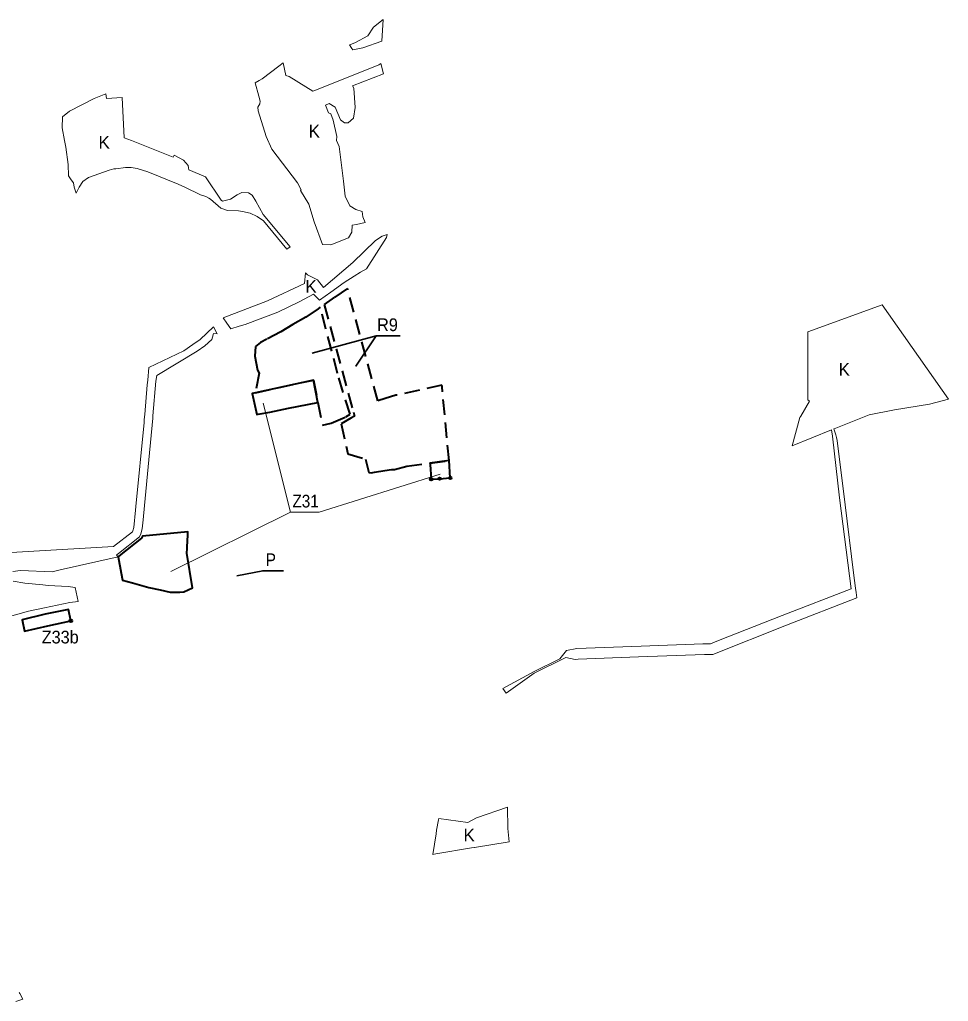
# Model space of a CAD drawing. Extents: x -650276 to -642489, y -1074311 to -1066658.
# Drawn here: x -644235 to -642489, y -1070870 to -1069023 of the extents above; entities that cross this region are included whole.
import ezdxf

# ---------------------------------------------------------------- set-up
doc = ezdxf.new("R2010")
doc.units = 0
doc.header["$LTSCALE"] = 9.6
doc.header["$PDMODE"] = 32
doc.header["$PDSIZE"] = 4.8
doc.linetypes.add('MEDIUM_DASHED', pattern=[4.5, 3, -1.5])
for name, color, linetype, lineweight in [('3', 7, 'Continuous', 40), ('45', 7, 'Continuous', 40), ('46', 7, 'Continuous', 13), ('47', 7, 'Continuous', 13), ('48', 7, 'Continuous', 35), ('59', 7, 'Continuous', 13), ('60', 7, 'Continuous', 35), ('61', 7, 'MEDIUM_DASHED', 40), ('62', 7, 'Continuous', 35)]:
    doc.layers.add(name, color=color, linetype=linetype, lineweight=lineweight)

msp = doc.modelspace()

# ---------------------------------------------------------------- linework, layer by layer
at = {"layer": '3'}
for p, q in [((-643461.327, -1069887.84), (-643445.37, -1069886.7)), ((-643445.37, -1069886.7), (-643425.253, -1069885.25))]:
    msp.add_line(p, q, dxfattribs=at)
for points in [[(-643425.253, -1069885.25), (-643427.6, -1069852.59), (-643463.51, -1069857.44)], [(-643463.51, -1069857.44), (-643463.31, -1069860.18), (-643461.327, -1069887.84)]]:
    msp.add_lwpolyline(points, dxfattribs=at)
for p in [(-643461.327, -1069887.84), (-643445.37, -1069886.7), (-643425.253, -1069885.25)]:
    msp.add_point(p, dxfattribs=at)
at = {"layer": '45'}
for p, q in [((-644138.78, -1070154.07), (-644143.31, -1070132.95)), ((-644182.31, -1070163.66), (-644138.78, -1070154.07))]:
    msp.add_line(p, q, dxfattribs=at)
for points in [[(-643791.88, -1069725.25), (-643797.75, -1069726.51), (-643789.3, -1069766.05), (-643786.35, -1069765.46), (-643764.94, -1069761.27), (-643729.34, -1069754.3), (-643674.3, -1069743.53), (-643682.61, -1069701.16)], [(-643791.88, -1069725.25), (-643797.75, -1069726.51), (-643789.3, -1069766.05), (-643786.35, -1069765.46), (-643764.94, -1069761.27), (-643729.34, -1069754.3), (-643674.3, -1069743.53), (-643682.61, -1069701.16)], [(-643920.84, -1070026.46), (-643920.29, -1070017.73), (-643920.16, -1070015.69), (-643918.69, -1069992.23), (-643918.88, -1069986.82), (-644004.06, -1069994.59), (-644005.92, -1069998.62), (-644044.7, -1070029.04), (-644050.12, -1070033.64), (-644044.18, -1070064.43), (-644041.71, -1070077.29), (-644022.77, -1070082.66), (-643991.99, -1070091.37), (-643971.03, -1070095.79), (-643951.99, -1070100.35), (-643933.96, -1070100.18), (-643926.33, -1070099.5), (-643909.87, -1070091.95)], [(-643920.84, -1070026.46), (-643920.29, -1070017.73), (-643920.16, -1070015.69), (-643918.69, -1069992.23), (-643918.88, -1069986.82), (-644004.06, -1069994.59), (-644005.92, -1069998.62), (-644044.7, -1070029.04), (-644050.12, -1070033.64), (-644044.18, -1070064.43), (-644041.71, -1070077.29), (-644022.77, -1070082.66), (-643991.99, -1070091.37), (-643971.03, -1070095.79), (-643951.99, -1070100.35), (-643933.96, -1070100.18), (-643926.33, -1070099.5), (-643909.87, -1070091.95)]]:
    msp.add_lwpolyline(points, close=True, dxfattribs=at)
for points in [[(-644143.31, -1070132.95), (-644143.31, -1070132.95), (-644143.31, -1070132.95), (-644187.11, -1070141.58), (-644230.4, -1070152.08), (-644226.23, -1070173.28), (-644182.31, -1070163.66)], [(-644143.31, -1070132.95), (-644143.31, -1070132.95), (-644143.31, -1070132.95), (-644187.11, -1070141.58), (-644230.4, -1070152.08), (-644226.23, -1070173.28), (-644182.31, -1070163.66)], [(-644182.31, -1070163.66), (-644138.78, -1070154.07), (-644143.31, -1070132.95)]]:
    msp.add_lwpolyline(points, dxfattribs=at)
msp.add_point((-644138.78, -1070154.07), dxfattribs=at)
at = {"layer": '46'}
msp.add_lwpolyline([(-643672.005, -1069949.473), (-643725.65, -1069949.473), (-643725.65, -1069949.473), (-643777.096, -1069744.435), (-643725.65, -1069949.473), (-643950.635, -1070061)], dxfattribs=at)
at = {"layer": '47'}
msp.add_line((-643785.6, -1069166.98), (-643782.92, -1069176.24), dxfattribs=at)
msp.add_lwpolyline([(-643589.94, -1069076.36), (-643554.17, -1069063.59), (-643551.72, -1069023.19), (-643569.44, -1069037.24), (-643580.21, -1069053.96), (-643603.72, -1069066.5), (-643614.36, -1069070.29), (-643614.82, -1069070.45), (-643610.31, -1069077.52), (-643608.65, -1069080.11)], close=True, dxfattribs=at)
for points in [[(-643697.29, -1069149.7), (-643728.49, -1069129.95), (-643734.75, -1069128.3), (-643739.66, -1069104.58), (-643747.75, -1069110.71), (-643779.31, -1069134.63), (-643784.55, -1069137.77), (-643792.04, -1069142.27), (-643785.6, -1069166.98)], [(-643555.98, -1069105.57), (-643559.5, -1069107.98), (-643610.81, -1069129.04), (-643681.63, -1069157.04), (-643683.68, -1069157.86), (-643697.29, -1069149.7)], [(-643607.02, -1069152.34), (-643609.08, -1069147.64), (-643550.79, -1069125.24), (-643555.98, -1069105.57)], [(-643707.23, -1069344.52), (-643691.6, -1069370.3), (-643681.09, -1069403.24), (-643665.87, -1069446.1), (-643650.28, -1069446.91), (-643616.78, -1069433.81), (-643610.18, -1069422.91), (-643609.6, -1069409.99), (-643601.9, -1069408.43), (-643585.19, -1069404.76), (-643589.52, -1069393.88), (-643590.89, -1069383.9), (-643602.92, -1069380.53), (-643614.35, -1069373.28), (-643623.28, -1069355.47), (-643625.9, -1069326.77), (-643634.56, -1069262.02), (-643639.23, -1069250.38), (-643638.72, -1069242.94), (-643645.61, -1069212.25), (-643649.84, -1069200.4), (-643654.57, -1069198.77), (-643660.22, -1069184.11), (-643653.05, -1069180.98), (-643641.84, -1069187.68), (-643631.66, -1069211.67), (-643624.38, -1069217.27), (-643617.64, -1069217), (-643607.37, -1069208.43), (-643604.38, -1069188.48), (-643607.02, -1069152.34)], [(-644094.79, -1069171.27), (-644141.24, -1069195.17), (-644154.36, -1069206.06), (-644155.37, -1069226.72), (-644151.11, -1069250.7), (-644148.22, -1069263.22), (-644144.05, -1069295.67)], [(-644024.93, -1069250.23), (-644038.83, -1069245.65), (-644042.37, -1069169.77), (-644071.97, -1069171.72), (-644073.35, -1069162.84), (-644094.79, -1069171.27)], [(-643782.92, -1069176.24), (-643783.2, -1069181.85), (-643786.97, -1069188.11), (-643786.89, -1069195.02), (-643771.86, -1069242.77), (-643761.21, -1069267.12), (-643712.78, -1069330.24)], [(-643732.705, -1069454.79), (-643726.74, -1069450.72), (-643777.27, -1069389.71), (-643791.02, -1069364.54), (-643798.1, -1069353.51), (-643804.83, -1069348.99), (-643817.06, -1069348.14), (-643826.21, -1069352.92), (-643838.69, -1069360.79), (-643853.56, -1069364.44), (-643856.43, -1069362.68), (-643885.63, -1069318.72), (-643916.78, -1069305.89), (-643917.36, -1069302.04), (-643918.08, -1069297.33), (-643926.74, -1069287.37), (-643944.89, -1069278.32), (-643946.16, -1069281.84), (-644015.12, -1069254.24), (-644024.93, -1069250.23)], [(-644144.05, -1069295.67), (-644143.54, -1069317.05), (-644138.55, -1069324.23), (-644134.15, -1069330.45), (-644132.52, -1069338.02), (-644129.09, -1069349.83), (-644123.21, -1069338.41), (-644116.33, -1069327.36), (-644105.5, -1069320.03), (-644067.08, -1069306.15)], [(-644067.08, -1069306.15), (-644058.05, -1069304.02), (-644054.35, -1069303.55)], [(-644054.35, -1069303.55), (-644035.89, -1069301.02), (-644025.24, -1069301.38), (-644014.19, -1069303.36), (-643993.91, -1069309.57), (-643936.87, -1069332.93), (-643924.42, -1069338.29), (-643894.84, -1069352.76), (-643885.22, -1069355.58), (-643879.48, -1069359.13), (-643876.34, -1069360.61), (-643856.58, -1069377.59), (-643844.28, -1069382.26), (-643823.72, -1069382.61), (-643815.93, -1069384.23), (-643801.36, -1069387.23), (-643788.63, -1069393.7), (-643776.78, -1069401.87), (-643732.705, -1069454.79)], [(-643712.78, -1069330.24), (-643705.74, -1069343.54), (-643707.23, -1069344.52)], [(-643671.53, -1069551.1), (-643649.94, -1069535.93), (-643624.65, -1069517.85), (-643605.97, -1069505.47), (-643594.49, -1069498.17), (-643582.77, -1069491.76), (-643545.07, -1069432.89), (-643544.06, -1069427.6), (-643553.7, -1069430.44), (-643565.92, -1069438.4), (-643608.89, -1069479.72), (-643663.46, -1069526.87), (-643675.32, -1069512.62), (-643693.95, -1069503.38)], [(-643693.95, -1069503.38), (-643697.85, -1069499.21), (-643699.23, -1069519.48), (-643769.08, -1069551.96), (-643852.51, -1069584.08), (-643845.304, -1069594.087)], [(-643845.304, -1069594.087), (-643837.72, -1069604.62), (-643822.06, -1069600.07), (-643811.16, -1069596.45), (-643749.64, -1069573.35), (-643709.33, -1069554.14), (-643682.27, -1069539.41), (-643671.53, -1069551.1)], [(-642704.1, -1069793.095), (-642703.57, -1069792.88), (-642693.99, -1069788.85), (-642637.44, -1069766.81), (-642589.86, -1069757.1), (-642524.14, -1069746.8), (-642488.71, -1069736.85), (-642613.34, -1069559.68), (-642753.18, -1069610.65), (-642753.25, -1069738.59), (-642750.08, -1069740.57), (-642766.27, -1069769), (-642767.89, -1069771.42), (-642782.69, -1069824.93)], [(-644248.05, -1070061.33), (-644233.51, -1070059.54), (-644174.12, -1070062.16), (-644159.02, -1070057.84), (-644050.12, -1070033.64), (-644053.18, -1070030.57), (-644051.913, -1070029.549), (-644049.311, -1070027.453), (-644009.95, -1069995.74), (-644006.96, -1069990.34), (-644005.06, -1069981.28), (-644003.06, -1069964.06), (-644000.52, -1069937.19), (-643992.27, -1069851.31), (-643984.845, -1069772.863), (-643984.44, -1069768.58), (-643978.85, -1069703.4), (-643977.454, -1069692.683), (-643901.55, -1069646.92), (-643886.62, -1069636.87), (-643873.82, -1069625.05), (-643872.55, -1069620.75), (-643870.44, -1069613.56), (-643863.92, -1069613.9), (-643870.697, -1069601.241), (-643895.951, -1069625.069), (-643909.616, -1069634.267), (-643926.229, -1069646.367), (-643992.34, -1069677.76), (-643994.36, -1069701.05), (-643995.17, -1069710.42), (-643999.94, -1069765.62), (-644000.79, -1069775.42), (-644001.04, -1069778.063), (-644001.29, -1069780.7), (-644016.47, -1069938.99), (-644017.15, -1069945.93), (-644020.26, -1069978.38), (-644022.43, -1069984.87), (-644022.99, -1069986.58), (-644058.55, -1070014.4), (-644219.33, -1070023.53), (-644370.87, -1070032.13)], [(-642706.3, -1069806.69), (-642693.2, -1069922.89), (-642671.23, -1070094.16), (-642801.19, -1070143.75), (-642921.03, -1070191.32), (-642936.02, -1070197.23), (-642942.12, -1070197.4), (-642950.42, -1070197.58), (-643066.26, -1070201.69), (-643187.06, -1070205.98)], [(-642782.69, -1069824.93), (-642708.257, -1069794.779), (-642706.3, -1069806.69)], [(-642662.32, -1070100.64), (-642663.28, -1070092.67), (-642667.19, -1070063.71), (-642682.78, -1069935.98), (-642697.64, -1069815.14), (-642698.77, -1069809.17), (-642700.34, -1069804.12), (-642704.1, -1069793.095)], [(-644381.21, -1070181.71), (-644218.65, -1070135.75), (-644188.44, -1070129.43), (-644140.72, -1070119.57), (-644125, -1070117.83), (-644130.91, -1070091.1), (-644144.13, -1070089.47), (-644181.81, -1070087.51), (-644191.26, -1070086.47), (-644225.13, -1070082.95), (-644247.3, -1070079.69)], [(-642936.88, -1070217.27), (-642931.88, -1070217.1), (-642792.87, -1070162.36), (-642661.13, -1070110.48), (-642662.32, -1070100.64)], [(-643187.06, -1070205.98), (-643207.1, -1070209.72), (-643219.4, -1070225.8), (-643267.55, -1070249.49), (-643326.26, -1070281.43), (-643320, -1070290.2), (-643267.75, -1070252.77), (-643208.09, -1070223.14), (-643190.42, -1070226.99)], [(-643190.42, -1070226.99), (-643184.86, -1070225.91), (-643071.16, -1070221.95), (-642947.42, -1070217.64), (-642936.88, -1070217.27)], [(-643452.22, -1070592.35), (-643385.72, -1070580.86), (-643380.35, -1070580.14), (-643380.08, -1070580.09), (-643314.51, -1070569.69), (-643315.27, -1070563.2), (-643317.08, -1070544.75), (-643317.9, -1070504.73)], [(-643317.9, -1070504.73), (-643376.07, -1070524.59), (-643392.41, -1070533.68), (-643446.89, -1070526.01)], [(-643446.89, -1070526.01), (-643447.79, -1070528.63), (-643450.98, -1070547.74), (-643452.14, -1070554.77)], [(-643452.14, -1070554.77), (-643458.42, -1070593.43), (-643452.22, -1070592.35)], [(-644242.29, -1070869.82), (-644229.12, -1070865.52), (-644234.66, -1070855.08), (-644236.3, -1070852.87)]]:
    msp.add_lwpolyline(points, dxfattribs=at)
at = {"layer": '59'}
msp.add_lwpolyline([(-643444.15, -1069878.232), (-643672.005, -1069949.473), (-643725.65, -1069949.473)], dxfattribs=at)
at = {"layer": '60'}
msp.add_lwpolyline([(-643738.691, -1070059.84), (-643778.124, -1070059.84), (-643826.476, -1070069.235)], dxfattribs=at)
msp.add_lwpolyline([(-643738.691, -1070059.84), (-643778.124, -1070059.84), (-643826.476, -1070069.235)], dxfattribs=at)
at = {"layer": '61'}
for points in [[(-643561.41, -1069740.406), (-643618.737, -1069528.647), (-643643.16, -1069545.42), (-643662.335, -1069558.944), (-643607.44, -1069761.72), (-643605.24, -1069768.92), (-643612.22, -1069772.9), (-643630.77, -1069783.44), (-643618, -1069840.01), (-643584.63, -1069849.66), (-643578.28, -1069874.97), (-643574.05, -1069875.85), (-643567.91, -1069874.7), (-643548.67, -1069871.08), (-643535.83, -1069869.23), (-643530.01, -1069869.17), (-643507.1, -1069863.33), (-643463.51, -1069857.44), (-643427.6, -1069852.59), (-643440.77, -1069713.85), (-643441.08, -1069710.59), (-643527.49, -1069729.78), (-643547.9, -1069735.62)], [(-643743.81, -1069610.19), (-643770.29, -1069624.14), (-643781.95, -1069630.63), (-643791.77, -1069637.88), (-643793.09, -1069656.07), (-643788.14, -1069682.71), (-643784.59, -1069688.47), (-643791.88, -1069725.25), (-643682.61, -1069701.16), (-643674.3, -1069743.53), (-643665.92, -1069785.96), (-643649.25, -1069782.43), (-643621.71, -1069770.11), (-643613.9, -1069765.6), (-643637.36, -1069688.73), (-643669.73, -1069564.16), (-643673.82, -1069567.04), (-643697, -1069582.64), (-643721.43, -1069596.72)]]:
    msp.add_lwpolyline(points, close=True, dxfattribs=at)
at = {"layer": '62'}
msp.add_lwpolyline([(-643519.721, -1069617.808), (-643564.914, -1069617.808), (-643602.876, -1069674.79), (-643564.914, -1069617.808), (-643685.127, -1069650.369)], dxfattribs=at)
at = {"layer": '62', "lineweight": 13}
msp.add_lwpolyline([(-643519.721, -1069617.808), (-643564.914, -1069617.808), (-643602.876, -1069674.79), (-643564.914, -1069617.808), (-643685.127, -1069650.369)], dxfattribs=at)

# ---------------------------------------------------------------- texts
at = {"layer": '46', "width": 0.95}
msp.add_text('Z33b', height=24, dxfattribs=at).set_placement((-644193.607, -1070196.61))
msp.add_text('Z33b', height=24, dxfattribs=at).set_placement((-644193.607, -1070196.61))
at = {"layer": '48'}
for p in [(-643691.928, -1069244.995), (-644086.887, -1069265.894), (-643697.851, -1069536.996), (-642695.251, -1069693.065), (-643400.597, -1070568.968), (-643400.597, -1070568.968)]:
    msp.add_text('K', height=24, dxfattribs=at).set_placement(p)
at = {"layer": '59', "width": 0.9}
msp.add_text('Z31', height=24, dxfattribs=at).set_placement((-643722.294, -1069940.847))
at = {"layer": '60', "width": 0.9}
msp.add_text('P', height=24, dxfattribs=at).set_placement((-643772.431, -1070051.2))
msp.add_text('P', height=24, dxfattribs=at).set_placement((-643772.431, -1070051.2))
at = {"layer": '62', "width": 0.95}
msp.add_text('R9', height=24, dxfattribs=at).set_placement((-643562.88, -1069609.148))
msp.add_text('R9', height=24, dxfattribs=at).set_placement((-643562.88, -1069609.148))

doc.saveas('drawing.dxf')
